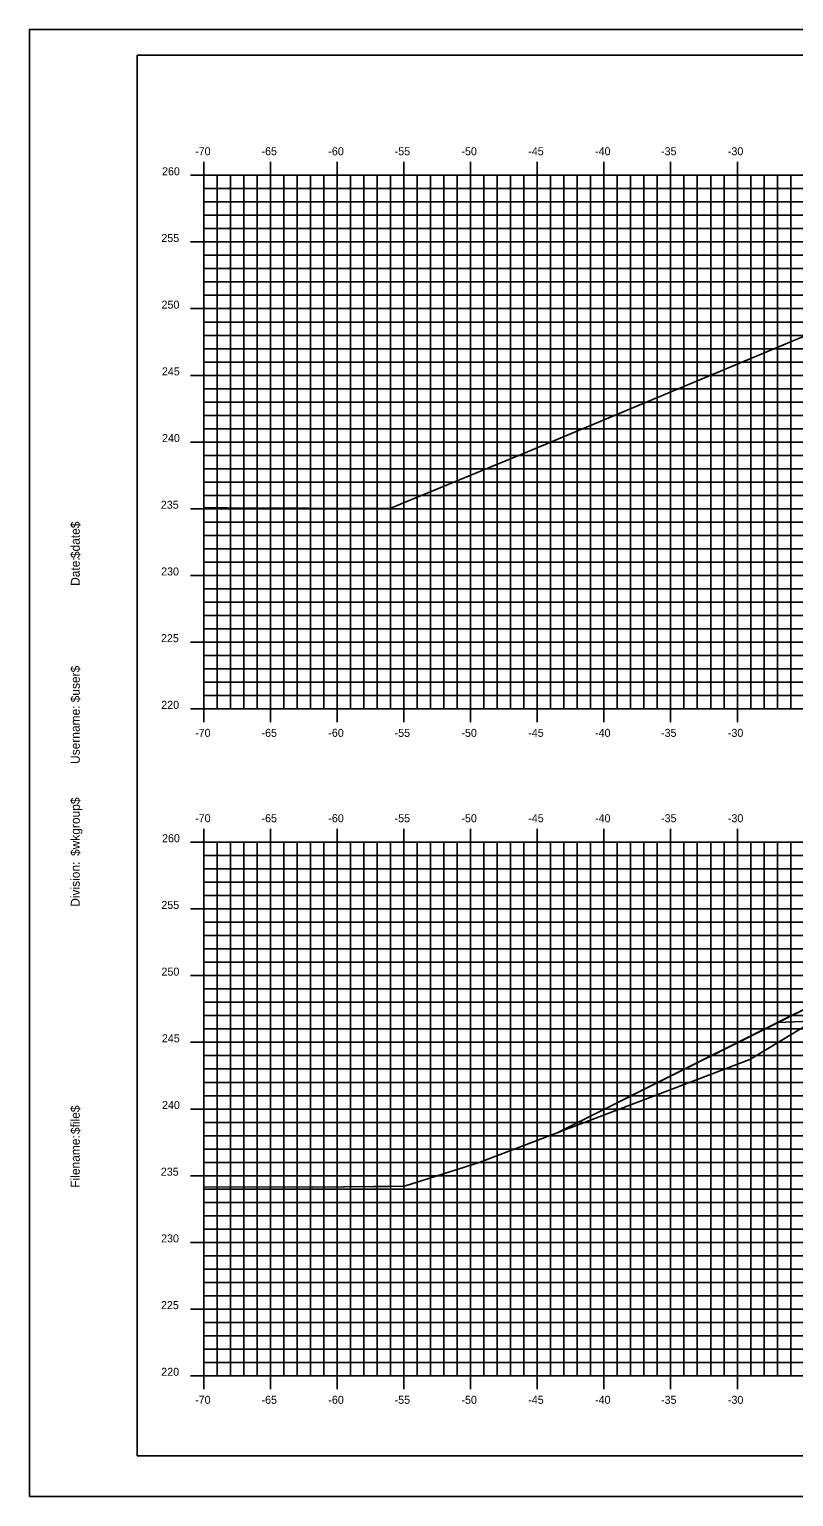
# Model space of a CAD drawing. Extents: x -22 to 1480, y -1511 to 8.
# Drawn here: x 992.1 to 1049.4, y -1511.4 to -1401.4 of the extents above; entities that cross this region are included whole.
import ezdxf

# ---------------------------------------------------------------- set-up
doc = ezdxf.new("R2010")
doc.units = 0
for name, color, linetype in [('BORDER', 7, 'Continuous'), ('D_Roadway_Centerline', 7, 'Continuous'), ('D_Roadway_SlopeLines', 7, 'Continuous'), ('D_Roadway_SubGrade', 7, 'Continuous'), ('H_V ANNOTATION', 7, 'Continuous'), ('MAJOR', 7, 'Continuous'), ('MINOR', 7, 'Continuous'), ('PLOT BOUNDARY', 7, 'Continuous'), ('S_Roadway_Centerline', 7, 'Continuous')]:
    doc.layers.add(name, color=color, linetype=linetype)

msp = doc.modelspace()

# ---------------------------------------------------------------- linework, layer by layer
at = {"layer": 'BORDER'}
for p, q in [((1160.18, -1403.33), (1000.18, -1403.33)), ((1000.18, -1403.33), (1000.18, -1508.33)), ((1000.18, -1508.33), (1160.18, -1508.33))]:
    msp.add_line(p, q, dxfattribs=at)
at = {"layer": 'D_Roadway_Centerline'}
msp.add_lwpolyline([(1031.76, -1484.07), (1041.45, -1479.23), (1045.25, -1477.33), (1048.2, -1475.85), (1049.88, -1475.02), (1054.18, -1472.86), (1056.34, -1472.78), (1057.18, -1472.74), (1058.86, -1472.68), (1063.18, -1472.5), (1066.54, -1472.44), (1075.18, -1472.26), (1078.54, -1472.33), (1087.18, -1472.5), (1089.98, -1472.62), (1097.18, -1472.9), (1098.02, -1472.94), (1100.18, -1473.02), (1101.86, -1473.86), (1106.16, -1476.01), (1115.5, -1480.68), (1121.28, -1483.57)], dxfattribs=at)
at = {"layer": 'D_Roadway_SlopeLines'}
msp.add_lwpolyline([(1054.18, -1472.86), (1031.76, -1484.07)], dxfattribs=at)
at = {"layer": 'D_Roadway_SubGrade'}
msp.add_lwpolyline([(1063.18, -1473.25), (1057.18, -1473.49), (1057.18, -1472.99), (1054.18, -1473.11), (1054.18, -1472.86), (1048.2, -1475.85), (1063.18, -1475.25)], close=True, dxfattribs=at)
at = {"layer": 'MAJOR'}
for p, q in [((1004.18, -1412.33), (1005.18, -1412.33)), ((1005.18, -1411.33), (1005.18, -1412.33)), ((1005.18, -1412.33), (1145.18, -1412.33)), ((1005.18, -1452.33), (1005.18, -1412.33)), ((1005.18, -1452.33), (1005.18, -1412.33)), ((1005.18, -1412.33), (1145.18, -1412.33)), ((1010.18, -1411.33), (1010.18, -1412.33)), ((1010.18, -1452.33), (1010.18, -1412.33)), ((1015.18, -1411.33), (1015.18, -1412.33)), ((1015.18, -1452.33), (1015.18, -1412.33)), ((1020.18, -1411.33), (1020.18, -1412.33)), ((1020.18, -1452.33), (1020.18, -1412.33)), ((1025.18, -1411.33), (1025.18, -1412.33)), ((1025.18, -1452.33), (1025.18, -1412.33)), ((1030.18, -1411.33), (1030.18, -1412.33)), ((1030.18, -1452.33), (1030.18, -1412.33)), ((1035.18, -1411.33), (1035.18, -1412.33)), ((1035.18, -1452.33), (1035.18, -1412.33)), ((1040.18, -1411.33), (1040.18, -1412.33)), ((1040.18, -1452.33), (1040.18, -1412.33)), ((1045.18, -1411.33), (1045.18, -1412.33)), ((1045.18, -1452.33), (1045.18, -1412.33)), ((1004.18, -1417.33), (1005.18, -1417.33)), ((1005.18, -1417.33), (1145.18, -1417.33)), ((1004.18, -1422.33), (1005.18, -1422.33)), ((1005.18, -1422.33), (1145.18, -1422.33)), ((1004.18, -1427.33), (1005.18, -1427.33)), ((1005.18, -1427.33), (1145.18, -1427.33)), ((1004.18, -1432.33), (1005.18, -1432.33)), ((1005.18, -1432.33), (1145.18, -1432.33)), ((1004.18, -1437.33), (1005.18, -1437.33)), ((1005.18, -1437.33), (1145.18, -1437.33)), ((1004.18, -1442.33), (1005.18, -1442.33)), ((1005.18, -1442.33), (1145.18, -1442.33)), ((1004.18, -1447.33), (1005.18, -1447.33)), ((1005.18, -1447.33), (1145.18, -1447.33)), ((1004.18, -1452.33), (1005.18, -1452.33)), ((1005.18, -1452.33), (1145.18, -1452.33)), ((1005.18, -1452.33), (1145.18, -1452.33)), ((1005.18, -1453.33), (1005.18, -1452.33)), ((1010.18, -1453.33), (1010.18, -1452.33)), ((1015.18, -1453.33), (1015.18, -1452.33)), ((1020.18, -1453.33), (1020.18, -1452.33)), ((1025.18, -1453.33), (1025.18, -1452.33)), ((1030.18, -1453.33), (1030.18, -1452.33)), ((1035.18, -1453.33), (1035.18, -1452.33)), ((1040.18, -1453.33), (1040.18, -1452.33)), ((1045.18, -1453.33), (1045.18, -1452.33)), ((1005.18, -1461.33), (1005.18, -1462.33)), ((1010.18, -1461.33), (1010.18, -1462.33)), ((1015.18, -1461.33), (1015.18, -1462.33)), ((1020.18, -1461.33), (1020.18, -1462.33)), ((1025.18, -1461.33), (1025.18, -1462.33)), ((1030.18, -1461.33), (1030.18, -1462.33)), ((1035.18, -1461.33), (1035.18, -1462.33)), ((1040.18, -1461.33), (1040.18, -1462.33)), ((1045.18, -1461.33), (1045.18, -1462.33)), ((1004.18, -1462.33), (1005.18, -1462.33)), ((1005.18, -1462.33), (1145.18, -1462.33)), ((1005.18, -1502.33), (1005.18, -1462.33)), ((1005.18, -1502.33), (1005.18, -1462.33)), ((1005.18, -1462.33), (1145.18, -1462.33)), ((1010.18, -1502.33), (1010.18, -1462.33)), ((1015.18, -1502.33), (1015.18, -1462.33)), ((1020.18, -1502.33), (1020.18, -1462.33)), ((1025.18, -1502.33), (1025.18, -1462.33)), ((1030.18, -1502.33), (1030.18, -1462.33)), ((1035.18, -1502.33), (1035.18, -1462.33)), ((1040.18, -1502.33), (1040.18, -1462.33)), ((1045.18, -1502.33), (1045.18, -1462.33)), ((1004.18, -1467.33), (1005.18, -1467.33)), ((1005.18, -1467.33), (1145.18, -1467.33)), ((1004.18, -1472.33), (1005.18, -1472.33)), ((1005.18, -1472.33), (1145.18, -1472.33)), ((1004.18, -1477.33), (1005.18, -1477.33)), ((1005.18, -1477.33), (1145.18, -1477.33)), ((1004.18, -1482.33), (1005.18, -1482.33)), ((1005.18, -1482.33), (1145.18, -1482.33)), ((1004.18, -1487.33), (1005.18, -1487.33)), ((1005.18, -1487.33), (1145.18, -1487.33)), ((1004.18, -1492.33), (1005.18, -1492.33)), ((1005.18, -1492.33), (1145.18, -1492.33)), ((1004.18, -1497.33), (1005.18, -1497.33)), ((1005.18, -1497.33), (1145.18, -1497.33)), ((1004.18, -1502.33), (1005.18, -1502.33)), ((1005.18, -1502.33), (1145.18, -1502.33)), ((1005.18, -1502.33), (1145.18, -1502.33)), ((1005.18, -1503.33), (1005.18, -1502.33)), ((1010.18, -1503.33), (1010.18, -1502.33)), ((1015.18, -1503.33), (1015.18, -1502.33)), ((1020.18, -1503.33), (1020.18, -1502.33)), ((1025.18, -1503.33), (1025.18, -1502.33)), ((1030.18, -1503.33), (1030.18, -1502.33)), ((1035.18, -1503.33), (1035.18, -1502.33)), ((1040.18, -1503.33), (1040.18, -1502.33)), ((1045.18, -1503.33), (1045.18, -1502.33))]:
    msp.add_line(p, q, dxfattribs=at)
at = {"layer": 'MINOR'}
for p, q in [((1006.18, -1452.33), (1006.18, -1412.33)), ((1007.18, -1452.33), (1007.18, -1412.33)), ((1008.18, -1452.33), (1008.18, -1412.33)), ((1009.18, -1452.33), (1009.18, -1412.33)), ((1011.18, -1452.33), (1011.18, -1412.33)), ((1012.18, -1452.33), (1012.18, -1412.33)), ((1013.18, -1452.33), (1013.18, -1412.33)), ((1014.18, -1452.33), (1014.18, -1412.33)), ((1016.18, -1452.33), (1016.18, -1412.33)), ((1017.18, -1452.33), (1017.18, -1412.33)), ((1018.18, -1452.33), (1018.18, -1412.33)), ((1019.18, -1452.33), (1019.18, -1412.33)), ((1021.18, -1452.33), (1021.18, -1412.33)), ((1022.18, -1452.33), (1022.18, -1412.33)), ((1023.18, -1452.33), (1023.18, -1412.33)), ((1024.18, -1452.33), (1024.18, -1412.33)), ((1026.18, -1452.33), (1026.18, -1412.33)), ((1027.18, -1452.33), (1027.18, -1412.33)), ((1028.18, -1452.33), (1028.18, -1412.33)), ((1029.18, -1452.33), (1029.18, -1412.33)), ((1031.18, -1452.33), (1031.18, -1412.33)), ((1032.18, -1452.33), (1032.18, -1412.33)), ((1033.18, -1452.33), (1033.18, -1412.33)), ((1034.18, -1452.33), (1034.18, -1412.33)), ((1036.18, -1452.33), (1036.18, -1412.33)), ((1037.18, -1452.33), (1037.18, -1412.33)), ((1038.18, -1452.33), (1038.18, -1412.33)), ((1039.18, -1452.33), (1039.18, -1412.33)), ((1041.18, -1452.33), (1041.18, -1412.33)), ((1042.18, -1452.33), (1042.18, -1412.33)), ((1043.18, -1452.33), (1043.18, -1412.33)), ((1044.18, -1452.33), (1044.18, -1412.33)), ((1046.18, -1452.33), (1046.18, -1412.33)), ((1047.18, -1452.33), (1047.18, -1412.33)), ((1048.18, -1452.33), (1048.18, -1412.33)), ((1049.18, -1452.33), (1049.18, -1412.33)), ((1005.18, -1413.33), (1145.18, -1413.33)), ((1005.18, -1413.33), (1006.18, -1413.33)), ((1005.18, -1414.33), (1145.18, -1414.33)), ((1005.18, -1414.33), (1006.18, -1414.33)), ((1005.18, -1415.33), (1145.18, -1415.33)), ((1005.18, -1415.33), (1006.18, -1415.33)), ((1005.18, -1416.33), (1145.18, -1416.33)), ((1005.18, -1416.33), (1006.18, -1416.33)), ((1005.18, -1418.33), (1145.18, -1418.33)), ((1005.18, -1418.33), (1006.18, -1418.33)), ((1005.18, -1419.33), (1145.18, -1419.33)), ((1005.18, -1419.33), (1006.18, -1419.33)), ((1005.18, -1420.33), (1145.18, -1420.33)), ((1005.18, -1420.33), (1006.18, -1420.33)), ((1005.18, -1421.33), (1145.18, -1421.33)), ((1005.18, -1421.33), (1006.18, -1421.33)), ((1005.18, -1423.33), (1145.18, -1423.33)), ((1005.18, -1423.33), (1006.18, -1423.33)), ((1005.18, -1424.33), (1145.18, -1424.33)), ((1005.18, -1424.33), (1006.18, -1424.33)), ((1005.18, -1425.33), (1145.18, -1425.33)), ((1005.18, -1425.33), (1006.18, -1425.33)), ((1005.18, -1426.33), (1145.18, -1426.33)), ((1005.18, -1426.33), (1006.18, -1426.33)), ((1005.18, -1428.33), (1145.18, -1428.33)), ((1005.18, -1428.33), (1006.18, -1428.33)), ((1005.18, -1429.33), (1145.18, -1429.33)), ((1005.18, -1429.33), (1006.18, -1429.33)), ((1005.18, -1430.33), (1145.18, -1430.33)), ((1005.18, -1430.33), (1006.18, -1430.33)), ((1005.18, -1431.33), (1145.18, -1431.33)), ((1005.18, -1431.33), (1006.18, -1431.33)), ((1005.18, -1433.33), (1145.18, -1433.33)), ((1005.18, -1433.33), (1006.18, -1433.33)), ((1005.18, -1434.33), (1145.18, -1434.33)), ((1005.18, -1434.33), (1006.18, -1434.33)), ((1005.18, -1435.33), (1145.18, -1435.33)), ((1005.18, -1435.33), (1006.18, -1435.33)), ((1005.18, -1436.33), (1145.18, -1436.33)), ((1005.18, -1436.33), (1006.18, -1436.33)), ((1005.18, -1438.33), (1145.18, -1438.33)), ((1005.18, -1438.33), (1006.18, -1438.33)), ((1005.18, -1439.33), (1145.18, -1439.33)), ((1005.18, -1439.33), (1006.18, -1439.33)), ((1005.18, -1440.33), (1145.18, -1440.33)), ((1005.18, -1440.33), (1006.18, -1440.33)), ((1005.18, -1441.33), (1145.18, -1441.33)), ((1005.18, -1441.33), (1006.18, -1441.33)), ((1005.18, -1443.33), (1145.18, -1443.33)), ((1005.18, -1443.33), (1006.18, -1443.33)), ((1005.18, -1444.33), (1145.18, -1444.33)), ((1005.18, -1444.33), (1006.18, -1444.33)), ((1005.18, -1445.33), (1145.18, -1445.33)), ((1005.18, -1445.33), (1006.18, -1445.33)), ((1005.18, -1446.33), (1145.18, -1446.33)), ((1005.18, -1446.33), (1006.18, -1446.33)), ((1005.18, -1448.33), (1145.18, -1448.33)), ((1005.18, -1448.33), (1006.18, -1448.33)), ((1005.18, -1449.33), (1145.18, -1449.33)), ((1005.18, -1449.33), (1006.18, -1449.33)), ((1005.18, -1450.33), (1145.18, -1450.33)), ((1005.18, -1450.33), (1006.18, -1450.33)), ((1005.18, -1451.33), (1145.18, -1451.33)), ((1005.18, -1451.33), (1006.18, -1451.33)), ((1006.18, -1502.33), (1006.18, -1462.33)), ((1007.18, -1502.33), (1007.18, -1462.33)), ((1008.18, -1502.33), (1008.18, -1462.33)), ((1009.18, -1502.33), (1009.18, -1462.33)), ((1011.18, -1502.33), (1011.18, -1462.33)), ((1012.18, -1502.33), (1012.18, -1462.33)), ((1013.18, -1502.33), (1013.18, -1462.33)), ((1014.18, -1502.33), (1014.18, -1462.33)), ((1016.18, -1502.33), (1016.18, -1462.33)), ((1017.18, -1502.33), (1017.18, -1462.33)), ((1018.18, -1502.33), (1018.18, -1462.33)), ((1019.18, -1502.33), (1019.18, -1462.33)), ((1021.18, -1502.33), (1021.18, -1462.33)), ((1022.18, -1502.33), (1022.18, -1462.33)), ((1023.18, -1502.33), (1023.18, -1462.33)), ((1024.18, -1502.33), (1024.18, -1462.33)), ((1026.18, -1502.33), (1026.18, -1462.33)), ((1027.18, -1502.33), (1027.18, -1462.33)), ((1028.18, -1502.33), (1028.18, -1462.33)), ((1029.18, -1502.33), (1029.18, -1462.33)), ((1031.18, -1502.33), (1031.18, -1462.33)), ((1032.18, -1502.33), (1032.18, -1462.33)), ((1033.18, -1502.33), (1033.18, -1462.33)), ((1034.18, -1502.33), (1034.18, -1462.33)), ((1036.18, -1502.33), (1036.18, -1462.33)), ((1037.18, -1502.33), (1037.18, -1462.33)), ((1038.18, -1502.33), (1038.18, -1462.33)), ((1039.18, -1502.33), (1039.18, -1462.33)), ((1041.18, -1502.33), (1041.18, -1462.33)), ((1042.18, -1502.33), (1042.18, -1462.33)), ((1043.18, -1502.33), (1043.18, -1462.33)), ((1044.18, -1502.33), (1044.18, -1462.33)), ((1046.18, -1502.33), (1046.18, -1462.33)), ((1047.18, -1502.33), (1047.18, -1462.33)), ((1048.18, -1502.33), (1048.18, -1462.33)), ((1049.18, -1502.33), (1049.18, -1462.33)), ((1005.18, -1463.33), (1145.18, -1463.33)), ((1005.18, -1463.33), (1006.18, -1463.33)), ((1005.18, -1464.33), (1145.18, -1464.33)), ((1005.18, -1464.33), (1006.18, -1464.33)), ((1005.18, -1465.33), (1145.18, -1465.33)), ((1005.18, -1465.33), (1006.18, -1465.33)), ((1005.18, -1466.33), (1145.18, -1466.33)), ((1005.18, -1466.33), (1006.18, -1466.33)), ((1005.18, -1468.33), (1145.18, -1468.33)), ((1005.18, -1468.33), (1006.18, -1468.33)), ((1005.18, -1469.33), (1145.18, -1469.33)), ((1005.18, -1469.33), (1006.18, -1469.33)), ((1005.18, -1470.33), (1145.18, -1470.33)), ((1005.18, -1470.33), (1006.18, -1470.33)), ((1005.18, -1471.33), (1145.18, -1471.33)), ((1005.18, -1471.33), (1006.18, -1471.33)), ((1005.18, -1473.33), (1145.18, -1473.33)), ((1005.18, -1473.33), (1006.18, -1473.33)), ((1005.18, -1474.33), (1145.18, -1474.33)), ((1005.18, -1474.33), (1006.18, -1474.33)), ((1005.18, -1475.33), (1145.18, -1475.33)), ((1005.18, -1475.33), (1006.18, -1475.33)), ((1005.18, -1476.33), (1145.18, -1476.33)), ((1005.18, -1476.33), (1006.18, -1476.33)), ((1005.18, -1478.33), (1145.18, -1478.33)), ((1005.18, -1478.33), (1006.18, -1478.33)), ((1005.18, -1479.33), (1145.18, -1479.33)), ((1005.18, -1479.33), (1006.18, -1479.33)), ((1005.18, -1480.33), (1145.18, -1480.33)), ((1005.18, -1480.33), (1006.18, -1480.33)), ((1005.18, -1481.33), (1145.18, -1481.33)), ((1005.18, -1481.33), (1006.18, -1481.33)), ((1005.18, -1483.33), (1145.18, -1483.33)), ((1005.18, -1483.33), (1006.18, -1483.33)), ((1005.18, -1484.33), (1145.18, -1484.33)), ((1005.18, -1484.33), (1006.18, -1484.33)), ((1005.18, -1485.33), (1145.18, -1485.33)), ((1005.18, -1485.33), (1006.18, -1485.33)), ((1005.18, -1486.33), (1145.18, -1486.33)), ((1005.18, -1486.33), (1006.18, -1486.33)), ((1005.18, -1488.33), (1145.18, -1488.33)), ((1005.18, -1488.33), (1006.18, -1488.33)), ((1005.18, -1489.33), (1145.18, -1489.33)), ((1005.18, -1489.33), (1006.18, -1489.33)), ((1005.18, -1490.33), (1145.18, -1490.33)), ((1005.18, -1490.33), (1006.18, -1490.33)), ((1005.18, -1491.33), (1145.18, -1491.33)), ((1005.18, -1491.33), (1006.18, -1491.33)), ((1005.18, -1493.33), (1145.18, -1493.33)), ((1005.18, -1493.33), (1006.18, -1493.33)), ((1005.18, -1494.33), (1145.18, -1494.33)), ((1005.18, -1494.33), (1006.18, -1494.33)), ((1005.18, -1495.33), (1145.18, -1495.33)), ((1005.18, -1495.33), (1006.18, -1495.33)), ((1005.18, -1496.33), (1145.18, -1496.33)), ((1005.18, -1496.33), (1006.18, -1496.33)), ((1005.18, -1498.33), (1145.18, -1498.33)), ((1005.18, -1498.33), (1006.18, -1498.33)), ((1005.18, -1499.33), (1145.18, -1499.33)), ((1005.18, -1499.33), (1006.18, -1499.33)), ((1005.18, -1500.33), (1145.18, -1500.33)), ((1005.18, -1500.33), (1006.18, -1500.33)), ((1005.18, -1501.33), (1145.18, -1501.33)), ((1005.18, -1501.33), (1006.18, -1501.33))]:
    msp.add_line(p, q, dxfattribs=at)
at = {"layer": 'PLOT BOUNDARY'}
msp.add_lwpolyline([(992.09, -1511.39), (1162.09, -1511.39), (1162.09, -1401.39), (992.09, -1401.39)], close=True, dxfattribs=at)
at = {"layer": 'S_Roadway_Centerline'}
for points in [[(1005.18, -1437.24), (1005.6, -1437.26), (1006.93, -1437.26), (1019.12, -1437.31), (1029.45, -1433.06), (1052.76, -1423.31)], [(1005.18, -1488.17), (1013.3, -1488.19), (1018.17, -1488.14), (1019.04, -1488.13), (1020.23, -1488.11), (1025.82, -1486.34), (1046.11, -1478.61), (1055.47, -1472.97)], [(1005.18, -1488.17), (1013.35, -1488.19), (1020.23, -1488.11), (1025.82, -1486.34), (1046.11, -1478.61), (1055.47, -1472.97)]]:
    msp.add_lwpolyline(points, dxfattribs=at)

# ---------------------------------------------------------------- texts
at = {"layer": 'BORDER'}
for s, p in [('$date$', (995.87, -1441.03)), ('Date:', (995.87, -1443.11)), ('$user$', (995.87, -1451.84)), ('Username:', (995.87, -1456.46)), ('$wkgroup$', (995.87, -1463.36)), ('Division:', (995.87, -1467.17)), ('$file$', (995.87, -1484.21)), ('Filename:', (995.87, -1488.23))]:
    msp.add_text(s, height=0.67, rotation=90, dxfattribs=at).set_placement(p)
at = {"layer": 'H_V ANNOTATION'}
for s, p in [('-70', (1004.52, -1410.83)), ('-65', (1009.5, -1410.83)), ('-60', (1014.51, -1410.83)), ('-55', (1019.48, -1410.83)), ('-50', (1024.49, -1410.83)), ('-45', (1029.5, -1410.83)), ('-40', (1034.51, -1410.83)), ('-35', (1039.46, -1410.83)), ('-30', (1044.47, -1410.83)), ('260', (1002.04, -1412.33)), ('255', (1001.99, -1417.33)), ('250', (1002, -1422.33)), ('245', (1002.03, -1427.33)), ('240', (1002.04, -1432.33)), ('235', (1001.95, -1437.33)), ('230', (1001.97, -1442.33)), ('225', (1001.96, -1447.33)), ('220', (1001.98, -1452.33)), ('-70', (1004.52, -1454.43)), ('-65', (1009.5, -1454.43)), ('-60', (1014.51, -1454.43)), ('-55', (1019.48, -1454.43)), ('-50', (1024.49, -1454.43)), ('-45', (1029.5, -1454.43)), ('-40', (1034.51, -1454.43)), ('-35', (1039.46, -1454.43)), ('-30', (1044.47, -1454.43)), ('-70', (1004.52, -1460.83)), ('-65', (1009.5, -1460.83)), ('-60', (1014.51, -1460.83)), ('-55', (1019.48, -1460.83)), ('-50', (1024.49, -1460.83)), ('-45', (1029.5, -1460.83)), ('-40', (1034.51, -1460.83)), ('-35', (1039.46, -1460.83)), ('-30', (1044.47, -1460.83)), ('260', (1002.04, -1462.33)), ('255', (1001.99, -1467.33)), ('250', (1002, -1472.33)), ('245', (1002.03, -1477.33)), ('240', (1002.04, -1482.33)), ('235', (1001.95, -1487.33)), ('230', (1001.97, -1492.33)), ('225', (1001.96, -1497.33)), ('220', (1001.98, -1502.33)), ('-70', (1004.52, -1504.43)), ('-65', (1009.5, -1504.43)), ('-60', (1014.51, -1504.43)), ('-55', (1019.48, -1504.43)), ('-50', (1024.49, -1504.43)), ('-45', (1029.5, -1504.43)), ('-40', (1034.51, -1504.43)), ('-35', (1039.46, -1504.43)), ('-30', (1044.47, -1504.43))]:
    msp.add_text(s, height=0.6, dxfattribs=at).set_placement(p)

doc.saveas('drawing.dxf')
